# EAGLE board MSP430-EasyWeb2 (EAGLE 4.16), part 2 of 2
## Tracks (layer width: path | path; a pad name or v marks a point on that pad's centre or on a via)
317_+3.3V  (via drill 0.61)
  Top 1.016: v37.21,16.38 37.21,17.4 36.7,17.91 32.51,17.91 32,17.4 3.3.1
  Top 1.27: 34.8,8.64 36.58,8.64 36.83,8.89 VR2.2 | 34.8,8.64 R54.2 | C30.2 34.8,8.64
  Bottom 1.27: v37.21,16.38 37.21,13.84 36.07,12.7 36.07,9.65 36.83,8.89 VR2.2
+3.3V  (via drill 0.81)
  Top 0.254: IC2.9 35.29,52.61 35.79,52.11 35.79,51.11 | 35.79,50.11 IC2.14 32.04,50.11 C20.1 | 35.79,50.11 35.79,51.11 | 35.79,51.11 IC2.12 | IC2.16 35.04,49.11 35.79,49.11 | 35.79,49.11 35.79,50.11 | 35.66,46.11 IC2.22 34.37,46.11 32.04,46.11 32.04,46.57 | 35.66,46.11 37.04,44.61 37.04,42.22 | IC2.29 | 37.54,42.22 IC2.29 | 37.04,42.22 IC2.28 | 37.04,42.22 37.54,42.22 | 35.79,48.9 35.66,46.11 | 35.79,48.9 35.79,49.11 | 32.04,46.57 32.04,46.61 | 32.04,46.57 C19.1 | 43.54,56.36 41.54,56.36 41.04,56.86 IC2.90 41.04,59.36 40.79,59.61 38.79,59.61 38.54,59.36 IC2.95 | IC2.85 | 43.54,56.36 IC2.85 | 48.04,56.36 IC2.76 48.04,58.97 48.79,59.72 48.79,60.64 R4.2 | 48.04,56.36 43.54,56.36 | 45.54,42.1 45.54,41.11 45.8,40.61 C16.1 46.46,40.61 47.04,40.61 47.54,41.11 IC2.49 | 45.54,42.1 IC2.45 | 45.54,42.1 46.04,42.1 IC2.46 46.04,47.11 | IC2.49 | 48.04,53.61 48.04,56.36 | 48.04,53.61 IC2.69 56.62,53.61 C23.1 | 46.04,47.11 46.04,50.11 48.04,52.11 48.04,53.61 | C22.1 37.68,40.61 37.54,40.61 IC2.29 | 41.04,44.36 IC2.36 | 41.04,44.36 38.04,44.36 37.54,43.86 37.54,42.22 | C21.1 52.04,47.26 52.04,47.11 | 52.04,47.11 IC2.56 48.54,47.11 46.04,47.11 | 52.04,45.72 52.04,45.61 | 52.04,45.72 C18.1 | 52.04,47.11 52.04,45.72 | 41.04,44.36 41.04,45.11 43.04,47.11 46.04,47.11 | v36.2,48.89 35.79,48.9
  Top 0.61: R4.2 C17.1
  Top 1.016: v32.51,19.68 31.62,19.68 30.86,18.92 3.3.2 | EXT.8 46.99,77.47 45.72,76.2 40.64,76.2 40.01,76.83 LINK.A
  Top 1.27: LAN.A LINK.A
  Bottom 1.016: 30.99,19.68 30.99,48.89 | 30.99,19.68 25.65,19.68 22.1,16.13 22.1,15.24 19.56,12.7 18.41,12.7 13.97,8.25 POWER.A | 30.99,19.68 v32.51,19.68 | 30.99,48.89 29.34,48.89 24.77,53.47 24.77,61.72 16.89,69.6 16.89,73.91 15.88,74.93 LAN.A | 30.99,48.89 v36.2,48.89
  pour Top (isolate 0.762, hatched): 35.56,60.33 35.56,44.45 55.88,44.45 55.88,64.14 41.91,64.14 41.91,60.33
+3.6V  (via drill 0.61, 0.81)
  Top 0.254: IC1.64 | 91.54,57.24 91.57,57.28 91.4,57.11 IC1.64 | 93.16,59.51 93.22,59.57 C14.1 | R8.2 94.23,52.32 94.23,52.58 | IC1.1 89.04,59.42 89.18,59.56
  Top 0.406: 91.54,57.24 91.54,58.89 91.54,59.56 | 91.54,59.56 89.18,59.56 89.15,59.56 | 93.22,59.57 93.22,59.56 91.54,59.56
  Top 0.61: R13.2 74.93,34.92 | 74.93,34.92 R37.2 | 74.93,34.92 U3.8 | U3.3 87.5,37.46 91.57,33.4 R14.2 91.44,32.51 | v96.14,52.58 94.23,52.58 | 93.26,59.69 C14.1 | 95.72,59.69 C13.1
  Top 0.813: U1.16 16.51,27.3 17.14,26.67 17.14,25.4 | 17.14,25.4 C15.1 | v17.14,23.49 17.14,25.4
  Top 1.016: R33.2 111.12,40.85 111.12,39.5 110.36,38.73 109.09,38.73 108.59,38.23 108.59,33.53 | 108.59,33.53 91.57,33.53 91.61,32.6 R14.2 | 108.59,31.24 R30.2 | 64,32.72 v64.01,31.62 | 108.59,10.79 108.59,5.08 106.05,2.54 100.97,2.54 100.33,3.17 JTAG.4 | 108.59,12.06 108.59,10.79 | 108.59,10.79 R24.2 | 108.59,21.08 R27.2 | 108.46,12.06 108.59,12.06 | 108.59,12.06 108.59,21.08 | 108.59,21.08 108.59,31.24 | 108.59,31.24 108.59,33.53 | 22.61,18.92 3.6.2
  Top 1.27: 47.62,32.73 58.54,32.71 R12.2 64,32.72 74.54,32.71 R13.2 | 47.62,32.73 R11.2 | 22.61,18.92 21.59,19.94 21.59,23.49 | v20.95,23.49 21.59,23.49 | 21.59,23.49 24.89,23.49 25.53,24.13 25.53,25.15 27.05,26.67 45.97,26.67 47.62,28.32 47.62,32.73 | 108.46,12.06 81.92,12.06 79.38,14.61 65.41,14.61 64.56,13.75 R34.2 64.56,11.85 62.87,10.16 D8.K | 94.49,59.69 93.26,59.69 | v94.49,60.33 94.49,59.69 | 94.49,59.69 95.72,59.69
  Bottom 0.61: 97.03,60.33 97.03,53.47 v96.14,52.58 | 97.03,60.33 97.03,65.41 92.58,69.85 92.58,73.03 97.79,78.23 AEXT.1 | 97.03,60.33 v94.49,60.33
  Bottom 0.813: v17.14,23.49 v20.95,23.49
  Bottom 1.016: v64.01,31.62 64.01,17.65 60.96,14.61 D8.K | AEXT.1 97.79,80.01 96.52,81.28 44.45,81.28 | 44.45,81.28 EXT.9 | 13.34,76.83 STATUS.A | 13.34,76.83 13.34,80.64 13.97,81.28 44.45,81.28 | 13.34,76.83 13.34,70.48 20.95,62.86 20.95,48.51 17.14,44.7 v17.14,23.49
+5V
  Top 1.016: LCD1.2 29.21,72.39 30.86,74.04 30.86,74.68 R38.2
  Top 1.27: C28.2 17.01,6.23 VR3.1
  Bottom 1.016: LCD1.2 29.21,69.85 30.48,68.58 47.24,68.58 47.24,73.28 49.53,75.56 EXT.7
  Bottom 1.27: VR3.1 17.14,6.1 17.14,8.25 18.41,9.52 26.04,9.52 31.11,14.61 31.11,15.88 36.2,20.95 36.2,43.18 47.24,54.23 47.24,68.58
+12V  (via drill 0.81)
  Top 1.27: 22.35,8.68 C27.2 | 22.35,8.68 22.35,12.06 20.07,14.35 C11.+ | D3.C 36.7,21.59 39.24,19.05 41.91,19.05 | 41.91,19.05 D10.K | VR1.3 29.97,5.84 29.97,7.37 28.66,8.68 C12.1 | VR3.3 21.84,6.22 21.84,8.64 22.35,8.68 | v105.28,30.73 105.28,23.37 103.51,21.59 95.89,21.59 93.35,19.05 41.91,19.05
  Bottom 1.27: VR1.3 29.21,4.32 27.81,2.92 21.97,2.92 20.7,4.19 VR3.3 | 105.28,44.83 102.87,47.24 LR2.A 101.6,48.89 100.33,50.16 100.33,52.7 102.23,54.61 106.05,54.61 107.32,55.88 107.32,62.23 | 105.28,44.83 REL2.1 | REL1.1 111.12,62.61 111.12,62.23 107.32,62.23 | 107.32,62.23 107.32,62.86 106.68,63.5 104.78,63.5 102.87,65.41 LR1.A 101.6,67.94 100.97,68.58 100.97,72.39 105.41,76.83 107.32,76.83 D5.K | C11.+ 20.07,18.16 D3.C | 105.28,40.64 D6.K | v105.28,30.73 105.28,40.64 | 105.28,40.64 105.28,44.83
/IOR  (via drill 0.61)
  Top 0.254: IC1.34 82.04,46.61 81.29,45.86 74.29,45.86 72.54,44.11 71.54,44.11 64.04,36.61 59.54,36.61 59.04,36.11 v58.04,36.11 | v57.79,48.86 56.06,48.86 55.31,49.61 IC2.61
  Bottom 0.254: 58.04,48.61 v57.79,48.86
  Bottom 0.406: v58.04,36.11 58.04,48.61
/IOW  (via drill 0.61)
  Top 0.254: IC1.35 82.54,46.61 82.54,46.36 81.54,45.36 74.79,45.36 72.79,43.36 71.79,43.36 64.04,35.61 v60.67,35.61 | IC2.62 | v58.54,50.11 IC2.62
  Bottom 0.406: v60.67,35.61 59.04,37.24 59.04,49.61 v58.54,50.11
A0
  Top 0.254: IC1.28 | IC1.28 71.54,51.61 67.54,47.61 62.54,47.61 62.54,46.99 R40.1
A1
  Top 0.254: IC1.29 | IC1.29 72.04,51.11 65.54,44.61 65.28,44.61 | R41.1 62.54,44.62
  Top 0.61: 62.54,44.62 65.28,44.61
A2
  Top 0.254: IC1.30 | IC1.30 72.54,50.61 64.04,42.11 63.5,42.11
  Top 0.61: R42.1 62.61,41.91 62.61,42.11 63.5,42.11
A3
  Top 0.254: IC1.31 | IC1.31 73.04,50.11 62.54,39.61 62.54,39.41 R43.1
AI0  (via drill 0.61)
  Top 0.254: IC1.59 92.29,54.61 93.29,55.61 95.54,55.61 v95.79,55.86
  Bottom 0.254: v95.79,55.86 95.79,57.11 93.29,59.61 93.29,67.73 | 95.29,78.06 AEXT.2
  Bottom 0.406: 93.29,67.73 91.52,69.51 91.52,73.86
  Bottom 0.61: 91.52,73.86 95.29,77.63 95.29,78.06
AI1  (via drill 0.61)
  Top 0.254: IC1.60 92.04,55.11 93.17,56.24 94.17,56.24 v94.54,56.61
  Bottom 0.254: v94.54,56.61 94.54,57.36 92.69,59.21 92.69,67.08
  Bottom 0.406: 92.69,67.08 90.64,69.13 90.64,74.33 90.64,74.64
  Bottom 0.61: AEXT.3 92.71,76.71 90.64,74.64
AI2  (via drill 0.61)
  Top 0.254: IC1.61 83.04,55.61 80.42,58.23 80.42,58.73 79.08,60.07 78.23,60.07 78.14,60.12 v78.14,60.25
  Bottom 0.406: 84.09,69.87 77.55,69.87 75.54,67.86 75.54,61.87 77.17,60.25 v78.14,60.25
  Bottom 0.61: 84.09,69.87 90.17,75.95 AEXT.4
AI3
  Top 0.254: IC1.2 | IC1.2 88.54,70.21 87.63,71.12
  Top 0.66: 87.63,71.12 AEXT.5
AI4
  Top 0.254: IC1.3 | IC1.3 88.04,69.11 85.04,72.11 | 85.04,78.05 AEXT.6
  Top 0.66: 85.04,72.11 85.04,78.05
AI5
  Top 0.254: IC1.4 | IC1.4 87.54,68.11 82.54,73.11 | 82.54,78.09 AEXT.7
  Top 0.66: 82.54,73.11 82.54,78.09
AI6
  Top 0.254: IC1.5 | IC1.5 87.04,67.11 80.04,74.11 | 80.04,78.71 AEXT.8
  Top 0.66: 80.04,74.11 80.04,78.71
AI7
  Top 0.254: IC1.6 | IC1.6 86.54,66.11 77.54,75.11 | 77.54,78.03 AEXT.9
  Top 0.66: 77.54,75.11 77.54,78.03
B1
  Top 0.254: IC1.40 | IC1.40 85.04,43.86 84.29,43.11 79.54,43.11 78.54,42.11 71.54,42.11 64.04,34.61 51.54,34.61 50.54,35.61 40.54,35.61
  Top 0.406: 39.54,34.61 40.54,35.61
  Top 0.813: 39.54,31.86 39.54,34.61 | 40.37,31.03 40.64,31.03
  Top 1.016: R11.1 40.64,31.03 B1.P$2 | 40.37,31.03 39.54,31.86
B2  (via drill 0.61)
  Top 0.254: IC1.41 85.54,43.61 84.54,42.61 79.79,42.61 78.79,41.61 72.42,41.61 v65.3,34.49
  Top 1.016: R12.1 57.15,29.76 B2.P$2
  Bottom 0.61: v65.3,34.49 61.54,34.49 57.15,30.1 B2.P$2
B3  (via drill 0.61)
  Top 0.254: IC1.42 86.04,43.36 84.79,42.11 80.04,42.11 79.04,41.11 73.18,41.11 71.04,38.98
  Top 0.406: v71.04,34.54 71.04,38.98
  Top 1.016: B3.P$2 73.66,29.59 74.93,30.86 R13.1
  Bottom 0.762: B3.P$2 72.14,29.21 71.04,30.31 v71.04,34.54
B4  (via drill 0.61)
  Top 0.254: IC1.43 86.54,43.11 84.91,41.48 80.91,41.48 v80.54,41.11
  Top 1.016: R14.1 91.57,30.61 B4.P$2
  Bottom 0.762: B4.P$2 85.85,29.21 80.54,34.52 80.54,35.89
  Bottom 0.813: 80.54,35.89 v80.54,41.11
D0  (via drill 0.61)
  Top 0.254: IC1.44 | IC1.44 87.04,42.86 85.04,40.86 81.66,40.86 80.92,40.11 v73.54,40.11 | 62.54,49.61 62.54,49.57 R44.1
  Top 0.406: 62.54,49.61 v68.04,49.61
  Bottom 0.406: v73.54,40.11 72.54,41.11 72.54,43.23 68.04,47.73 v68.04,49.61
D1  (via drill 0.61)
  Top 0.254: IC1.45 | IC1.45 87.54,42.61 85.16,40.23 82.04,40.23 81.42,39.61 74.54,39.61 74.04,39.11 v72.54,39.11
  Top 0.406: v66.54,51.11 65.54,52.11
  Top 0.61: R45.1 62.54,52.11 65.54,52.11
  Bottom 0.406: v72.54,39.11 71.04,40.61 71.04,42.34 66.54,46.84 v66.54,51.11
D2  (via drill 0.61)
  Top 0.254: IC1.46 88.04,48.61 87.92,48.73 81.41,48.73 79.54,46.86 73.29,46.86 72.79,46.36 v72.29,46.36
  Top 0.406: 65.29,54.61 v68.29,51.61
  Top 0.61: R46.1 65.29,54.61
  Bottom 0.406: v72.29,46.36 69.8,48.85 69.8,50.1 v68.29,51.61
D3  (via drill 0.61)
  Top 0.254: IC1.47 88.54,48.86 88.05,49.35 81.28,49.35 79.54,47.61 74.54,47.61 74.29,47.86 v73.54,47.86
  Top 0.406: 62.71,57.02 62.62,57.11 | 65.79,57.02 v66.94,55.84
  Top 0.61: 62.62,57.11 R47.1 | 62.71,57.02 65.79,57.02
  Bottom 0.406: v66.94,55.84 66.94,55 71.5,50.42 71.5,49.9 v73.54,47.86
D4  (via drill 0.61)
  Top 0.254: IC1.48 89.04,49.11 88.18,49.98 81.16,49.98 79.79,48.61 v75.29,48.61 | 62.66,59.61 R48.1
  Top 0.406: v69.54,54.36 69.54,55.36 65.29,59.61
  Top 0.61: 62.66,59.61 65.29,59.61
  Bottom 0.406: v69.54,54.36 v75.29,48.61
D5  (via drill 0.61)
  Top 0.254: IC1.49 91.54,49.61 92.04,49.11 92.04,48.48 91.54,47.98 v91.04,47.98
  Top 0.406: 64.42,62.23 65.92,60.73 68.99,60.73 69.09,60.83 v69.04,60.86
  Top 0.61: R49.1 64.42,62.23
  Bottom 0.406: v91.04,47.98 89.92,46.86 89.92,43.56 89.41,43.05 87.5,43.05 86.49,44.07 86.49,44.96 83.31,48.13 81.79,48.13 81.79,48.11 v69.04,60.86
D6  (via drill 0.61)
  Top 0.254: IC1.50 92.04,50.11 92.79,49.36 92.79,47.7 92.08,46.99 v92.07,47 v92.06,47 | 62.74,64.61 R50.1
  Top 0.406: v67.04,61.86 64.29,64.61
  Top 0.61: 64.29,64.61 62.74,64.61
  Bottom 0.254: v67.04,61.86 67.04,60.36 80.66,46.74 82.8,46.74 84.71,44.83 84.71,43.56 86.61,41.66 89.92,41.66 92.06,43.8 v92.06,47
D7  (via drill 0.61)
  Top 0.254: IC1.51 92.29,50.61 93.54,49.36 93.54,46.68 92.84,45.97 v91.02,45.97 v91.02,45.98 | 62.54,67.11 62.54,67.27 R51.1
  Top 0.406: v68.04,62.86 63.79,67.11
  Top 0.61: 63.79,67.11 62.54,67.11
  Bottom 0.254: v68.04,62.86 68.04,60.36 81.04,47.36 81.79,47.37 83.06,47.37 85.47,44.96 85.47,43.69 86.87,42.29 89.66,42.29 90.93,43.56 90.93,45.98 v91.02,45.98
DALLAS  (via drill 0.61)
  Top 0.254: IC1.19 77.29,56.11 v76.79,56.61
  Top 0.813: R35.2 71.75,13.11 v72.82,13.11
  Bottom 0.254: v76.79,56.61 69.54,63.86 67.29,63.86 66.04,62.61 66.04,60.36 77.29,49.11 77.29,42.61 78.79,41.11 78.79,35.23
  Bottom 0.406: 75.57,32.01 78.79,35.23
  Bottom 0.61: v72.82,13.11 72.82,15.99 70.95,17.86 70.95,25.13 72.36,26.54 74.42,26.54 75.57,27.69 75.57,32.01
DI1  (via drill 0.61)
  Top 0.254: IC1.13 83.04,60.51 81.54,62.01 v81.54,63.5
  Top 1.27: v114.55,10.16 113.92,10.79 R24.1
  Bottom 0.254: 81.53,62.74 81.54,63.11 v81.54,63.5 | 102.16,29.73 102.16,38.78 102.79,39.42 102.79,43.11 97.54,48.36 96.06,48.36 84.73,59.69 83.95,59.69 81.53,62.1 81.53,62.74 | 81.53,62.74 81.53,62.86
  Bottom 0.406: 102.16,29.73 104.79,27.1 104.79,9.48 105.41,8.86 114.55,8.86
  Bottom 1.27: OK1.5 119.38,9.14 118.62,8.38 114.55,8.38 114.55,8.86 v114.55,10.16
DI2  (via drill 0.61)
  Top 0.254: IC1.14 82.54,60.26 80.54,62.26 80.54,64.67 80.52,64.64 v80.54,64.74
  Top 1.27: R27.1 113.67,21.08 v114.43,20.32
  Bottom 0.254: v80.54,64.74 82.07,64.74 82.55,64.26 82.55,62.1 84.33,60.33 85.09,60.33 96.31,49.11 97.91,49.11 103.53,43.49 103.53,39.02 103,38.48 103,30.1 112.78,20.32 113.54,20.32 113.7,20.32 113.8,20.32 114.43,20.33 v114.43,20.32
  Bottom 1.016: OK2.5 119.38,19.68 118.24,18.54 116.21,18.54 v114.43,20.32
DI3  (via drill 0.61)
  Top 0.254: IC1.15 82.04,59.96 79.79,62.21 79.79,64.23 79.04,64.97 v79.04,65.37
  Top 1.27: v114.43,30.48 113.67,31.24 R30.1
  Bottom 0.254: v79.04,65.37 v79.04,65.36 79.38,65.66 79.46,65.74 82.05,65.74 83.57,64.22 83.57,62.1 84.71,60.96 85.34,60.96 96.44,49.86 98.29,49.86 104.16,43.99 104.16,38.62 103.63,38.1 103.63,30.61 103.65,30.61 105.65,28.61 109.04,28.61 109.13,28.7 114.43,28.7
  Bottom 0.813: OK3.5 119.38,29.84 118.24,28.7 114.43,28.7 v114.43,30.48
DI4  (via drill 0.61)
  Top 0.254: IC1.16 81.54,59.61 79.12,61.98 79.12,62.54 78.66,63 v78.66,63.75 | 113.29,42.61 113.29,42.55
  Top 0.406: v101.79,42.61 113.29,42.61
  Top 1.27: OK4.5 119.38,41.27 118.11,42.55 113.29,42.55 113.28,41.53 R33.1
  Bottom 0.254: v101.79,42.61 101.8,42.61 96.93,47.48 96.06,47.48 84.49,59.05 83.57,59.05 78.87,63.75 78.67,63.75 v78.66,63.75
E
  Top 0.254: IC1.23 74.54,54.11 73.54,55.11 73.54,65.61 64.89,74.26 51.02,74.26 47.88,71.12 47.62,71.12
  Top 0.61: LCD1.6 47.62,71.12
ETH_RES
  Top 0.254: IC2.75 50.54,56.61 52.66,58.73 52.66,62.36 | 51.54,62.36 51.45,62.44 C17.2 | 54.04,62.36 53.98,62.42 R9.2
  Top 0.813: 51.54,62.36 52.66,62.36 54.04,62.36
FREQ  (via drill 0.61)
  Top 0.254: IC1.12 83.54,58.11 83.29,57.86 81.54,57.86 81.04,58.36 81.04,59.16 80.85,59.36 78.49,61.72 78.52,61.75 v78.15,61.75 v78.16,61.75
  Top 1.27: R36.2 74.3,12.28 FREQ.2
  Bottom 0.254: v78.16,61.75 78.83,61.75 82.92,57.66 84.01,57.66 94.81,46.86 94.87,46.74 94.87,43.94 91.31,40.39 88.9,40.39 88.01,39.5 88.01,39.37
  Bottom 0.406: 92.2,21.27 92.2,30.61 88.01,34.8 88.01,39.37
  Bottom 0.762: 76.01,5.08 92.2,21.27
  Bottom 1.016: FREQ.2 76.01,5.08
GND  (via drill 0.61, 0.64, 0.81)
  Top 0.254: IC2.89 | IC2.89 41.54,57.36 41.91,56.99 42.67,56.99 43.04,57.36 IC2.86 43.04,61.52 43.81,62.29 | IC2.89 41.54,59.61 41.54,59.86 41.16,60.24 38.67,60.24 38.04,59.61 IC2.96 38.04,57.37 38.29,57.11 38.79,57.11 39.04,57.36 IC2.94 | IC2.1 33.66,56.61 33.66,56.11 34.04,56.11 IC2.2 33.29,56.11 33.02,55.84 33.02,54.11 | 33.53,53.61 IC2.7 33.02,53.61 | 33.53,53.11 IC2.8 33.02,53.11 | IC2.10 32.79,52.11 33.02,52.11 33.02,53.11 | 33.28,45.11 IC2.24 | 33.28,45.11 33.28,44.61 IC2.25 35.54,44.61 36.04,44.11 36.04,42.22 | IC2.23 33.28,45.61 33.28,45.11 | C19.2 32.04,45.11 33.28,45.11 | IC2.27 | IC2.27 36.54,42.22 36.04,42.22 | 36.04,42.22 IC2.26 | IC2.41 | 43.54,40.7 C16.2 | 43.54,40.7 43.54,42.09 | 43.54,42.09 IC2.41 | IC2.41 43.54,43.11 43.54,42.09 | 43.54,42.09 44.04,42.09 | 44.04,42.09 IC2.42 | 44.04,42.09 44.54,42.09 | IC2.43 44.54,43.11 44.54,42.09 | IC2.44 45.04,42.09 44.54,42.09 | 50.04,44.61 IC2.51 48.42,44.61 48.04,44.23 48.04,43.94 | 50.04,44.61 50.04,45.11 | 50.04,45.11 IC2.52 | 50.04,45.11 50.04,45.61 | 50.04,45.61 IC2.53 | 50.04,45.61 50.04,46.11 | IC2.55 50.04,46.61 50.04,46.11 | 50.04,46.11 | 50.04,46.11 IC2.54 | IC2.57 50.04,47.61 50.04,48.11 | 50.04,48.11 IC2.58 | IC2.58 | 50.04,48.61 50.04,48.11 | 50.04,49.11 IC2.60 48.79,49.11 48.54,49.36 48.54,50.36 48.79,50.61 IC2.63 | 50.04,48.61 IC2.59 | 50.04,49.11 50.04,48.61 | 50.04,45.11 | 52.54,54.11 IC2.70 54.04,54.11 | 52.54,54.11 | C23.2 55.24,54.61 55.16,54.11 54.04,54.11 | 54.04,54.11 52.54,54.11 | C22.2 36.2,40.64 36.54,40.93 IC2.27 | 43.54,40.7 43.54,39.61 43.79,39.36 47.29,39.36 48.04,40.11 IC2.50 48.04,43.94 | 50.04,49.11 | 50.04,44.61 50.54,44.61 50.54,44.11 51.04,43.61 53.13,43.61 53.55,44.03 C18.2
  Top 0.254: 50.54,49.11 50.04,49.11 | 50.54,49.11 | IC1.62 | IC1.62 92.05,56.11 92.05,56.61 | IC1.63 | 92.05,56.61 IC1.63 | 46.35,62.48 R5.2 46.35,62.29 | 54.04,54.11 | v54.04,54.61 54.04,54.11 | 92.16,56.61 92.05,56.61 | 89.92,56.61 83.79,56.61 v83.57,56.64 | IC1.63 89.92,56.61 89.92,56.62 89.92,56.6 89.92,56.61 | 89.92,56.61 91.04,56.61 | IC2.21 33.27,46.61 33.15,46.74 33.15,47.11 | 33.15,47.11 IC2.20 | 33.15,47.61 33.15,47.11 | 33.15,47.61 IC2.19 | IC2.18 33.15,48.11 33.15,47.61 | 50.54,49.11 53.25,49.11 53.55,48.81 C21.2 | 98.17,37.21 95.89,37.21 v95.89,35.56 v100.84,35.56 | 33.02,54.11 IC2.6 | 33.02,53.61 33.02,54.11 | 33.02,53.11 33.02,53.61 | IC2.47 46.54,41.85 46.61,41.78 46.99,41.78 47.04,41.83 IC2.48 47.04,43.87 47.12,43.94 48.04,43.94
  Top 0.305: 82.55,38.73 82.55,38.74 82.55,38.48
  Top 0.406: 32.79,52.11 32.42,52.11 32,51.69 31.75,51.69 C20.2 | 92.16,56.61 92.79,57.24 92.79,57.61 C14.2 | 28.83,53.98 C2.2 | 32.26,48.11 33.15,48.11
  Top 0.61: 20.07,36.2 U1.8 | C9.2 25.18,36.74 | C13.2 95.57,58.27 93.41,58.27 C14.2 | 36.83,69.22 40.64,69.22 43.81,66.04 43.81,64.77 | 43.81,64.77 43.81,62.29 46.35,62.29 | U3.7 82.55,36.2 U3.2 | 85.73,38.73 U3.4 82.55,38.73 | 19.05,28.58 U1.15 | 15.88,34.92 U1.10 14.61,34.92 14.1,35.43 14.1,39.78 | 43.81,64.77 54.61,64.77 | 54.61,64.77 55.5,63.88 55.5,61.09 55.12,60.71 53.98,60.71 | 54.61,64.77 v54.61,66.42 | 20.19,18.29 C31.- | 82.55,34.92 U3.1 | 25.36,29.55 C10.2 | C18.2 C21.2
  Top 0.66: 25.18,36.74 26.42,37.97 27.69,37.97 28.57,37.08 28.57,31.92 28.03,31.37 27.18,31.37 25.36,29.55 | U1.8 C9.2
  Top 0.813: 19.05,25.4 19.05,28.58 19.05,35.05 20.07,36.2 | 88.14,38.73 89.66,37.21 93.47,37.21 | 93.47,37.21 98.17,37.21 99.19,38.23 99.19,43.56 98.07,44.68 98.07,52.45 98.04,52.48 98.04,54.23 C6.2 | 82.55,38.73 87.5,38.73 | 88.14,38.73 88.14,38.74 | R9.1 53.98,60.71 54.04,60.64 | C32.1 87.5,40.39 87.5,38.73 | 87.5,38.73 88.14,38.73 | 29.97,48.11 32.26,48.11 | 93.47,37.21 C33.1
  Top 1.016: v39.37,74.93 R39.1 37.72,74.89 37.72,72.64 36.83,71.75 LCD1.5 36.83,69.22 26.67,69.22 | C19.2 31.75,44.83 29.97,44.83 29.97,48.11 29.97,51.65 | OK1.4 R23.1 | OK2.4 R26.1 | OK3.4 R29.1 | OK4.4 R32.1 | PWR.-- 9.4,7.75 | EXT.10 41.91,80.01 43.18,81.28 66.04,81.28 67.31,80.01 AEXT.13 | 98.08,57.95 C13.2 | 98.08,57.95 98.43,58.29 v98.43,59.05 98.43,60.96 96.52,62.86 C5.1 C4.2 | 98.07,52.45 98.08,57.95 | 26.67,69.22 26.67,67.94 22.86,64.14 C3.2 | 26.67,69.22 LCD1.1 | 54.04,60.64 v54.04,59.61 | C3.2 | C3.2 22.86,53.21 22.86,51.65 | 22.86,51.65 v22.86,49.91 19.05,46.1 17.14,46.1 14.1,42.93 14.1,39.78 RS232.5 11.79,39.78 11.18,40.39 7.24,40.39 6.22,39.37 PWR.- | 22.86,51.65 28.83,51.65 | 28.83,51.65 29.97,51.65 | 28.83,51.65 28.83,53.98 | R10.1 7.49,8 | 29.97,51.65 C20.2 | 19.05,18.29 20.19,18.29 | v56.39,45.09 C18.2
  Top 1.27: 24.13,2.67 R52.1 | 16.51,10.41 C28.1 17.11,10.41 16.51,10.41 | 16.51,10.41 18.8,10.41 | 18.8,10.41 C27.1 | 16.51,10.41 C11.- 19.05,18.29 19.05,25.4 C15.2 | T1.1 R17.1 | T2.1 R20.1 | 18.8,10.41 18.8,7.62 VR3.2 | 14.99,9.52 15.88,10.41 16.51,10.41 | 64.14,2.67 DALLAS.1 | 64.14,2.67 71.76,2.67 | D9.A 78.11,5.21 75.57,2.67 71.76,2.67 | 71.76,2.67 FREQ.1 | R36.1 76.84,12.7 78.11,11.43 D9.A | D9.A 92.71,10.16 | 92.71,10.16 v106.17,10.16 | 82.55,38.48 82.55,38.73 82.55,36.2 82.55,34.92 82.55,24.13 | 34.8,2.67 32.26,2.67 R55.1 31.2,8.68 29.84,10.03 29.84,10.38 | 34.8,2.67 35.56,1.9 63.37,1.9 64.14,2.67 | 34.8,2.67 C30.1 | 82.55,24.13 81.41,24.13 78.49,21.21 73.66,21.21 | 82.55,24.13 B4.P$1 | B3.P$1 73.66,21.21 | B1.P$1 43.56,21.21 57.15,21.21 | 73.66,21.21 57.15,21.21 | 57.15,21.21 B2.P$1 | 92.71,10.16 JTAG.9 | 29.84,12.87 C26.2 | 29.84,12.87 C29.1 | 29.84,10.38 C12.2 | 29.84,10.38 29.84,12.87
  Top 1.676: 14.73,8 14.99,8
  Top 1.778: 32.26,2.67 24.13,2.67 17.4,2.67 14.99,5.08 14.99,8 14.99,9.52
  Top 2.184: PWR.-- 14.73,8
  Top 2.54: PWR.- 6.22,9.27 7.49,8 PWR.--
  Bottom 0.406: v54.04,59.61 v54.04,54.61
  Bottom 1.016: v39.37,74.93 39.37,75.56 EXT.10 | v98.43,59.05 105.41,59.05 | v56.39,45.09 56.39,37.85 54.23,35.69 54.23,27.05 B2.P$1
  Bottom 1.27: T2.1 105.41,59.05 T1.1 | OK4.4 124.46,40.64 126.37,38.73 126.37,30.48 | 126.37,30.48 OK3.4 | 126.37,20.32 126.37,30.48 | 126.37,20.32 OK2.4 121.92,19.05 119.76,16.89 115.57,16.89 113.79,18.67 108.59,18.67 107.32,17.4 107.32,11.3 v106.17,10.16 | 126.37,20.32 126.37,12.7 123.83,10.16 OK1.4 | FREQ.1 71.76,7.62 74.3,10.16 74.3,18.16 73.66,18.8 B3.P$1
  pour Bottom (isolate 0.61, rank 2, hatched): -0.63,-1.27 108.59,-1.27 108.59,40.64 103.51,40.64 103.51,82.55 -0.63,82.55
  pour Top (isolate 0.61, rank 2, hatched): -1.27,-1.27 107.7,-1.27 107.7,41.91 103.51,41.91 103.51,82.55 -1.27,82.55
GNDA
  Top 1.27: C25.1 7.26,72.39 6.86,72.39 RJ45.G1 RJ45.G2 4.95,51.44 C24.1
LANLED  (via drill 0.61)
  Top 0.254: IC2.100 36.04,59.11 35.67,59.48
  Top 0.305: 33.81,59.48 35.67,59.48
  Top 0.406: 33.81,59.48 32.18,61.11 30.68,61.11 v29.54,62.25
  Top 0.61: v24.89,68.2 24.89,72.26 25.65,73.03 27.56,73.03 28.14,73.62 R6.1
  Bottom 0.406: v29.54,62.25 29.59,62.23 29.59,63.25 29.57,63.52 29.08,64.01 v24.89,68.2
LCD_D4
  Top 0.254: IC1.24 74.04,53.61 72.79,54.86 72.79,65.36 64.57,73.58 64.44,73.66 54.61,73.66 54.47,73.58 | 52,71.11 52.01,71.12 LCD2.1
  Top 0.406: 52.01,71.12 54.47,73.58
LCD_D5
  Top 0.254: IC1.25 | IC1.25 73.54,53.11 72.04,54.61 72.04,65.11 63.99,73.16 63.99,73.15 56.52,73.15 56.42,73.03 | 54.5,71.11 LCD2.2
  Top 0.406: 54.5,71.11 56.42,73.03
LCD_D6
  Top 0.254: IC1.26 73.04,52.61 71.29,54.36 71.29,64.86 63.67,72.48 63.67,72.52 58.55,72.52 58.34,72.31
  Top 0.66: 58.34,72.31 LCD2.3
LCD_D7
  Top 0.254: IC1.27 72.54,52.11 70.54,54.11 70.54,64.61 64.04,71.11 62.24,71.11
  Top 0.61: 62.24,71.11 LCD2.4
LINKLED  (via drill 0.61)
  Top 0.254: IC2.99 36.54,59.48 36.54,59.61 36.04,60.11
  Top 0.305: v31.28,62.25 31.24,62.23 32.51,62.23 34.63,60.11 36.04,60.11
  Top 0.406: v31.37,79.63 R7.1
  Bottom 0.406: v31.28,62.25 31.28,63.66 25.01,69.92 25.01,72.25 27.69,74.93 29.21,74.93 31.37,77.09 v31.37,79.63
N$1
  Top 1.016: R10.2 11.21,2.32 POWER.K
N$2
  Top 0.66: R7.2 23.11,79.63 LINK.K
N$3
  Top 1.016: R6.2 15.11,74.93 14.1,75.95 14.1,78.11 15.37,79.38 LAN.K
N$4
  Top 2.54: D3.A 15.88,19.05 13.97,17.14 13.97,13.97 PWR.+
N$5
  Top 0.61: U1.1 23.49,27.3 23.71,27.09 C7.2
N$6
  Top 0.66: U1.4 25.4,31.12 26.54,32.26 26.54,32.8 C8.2
N$7
  Top 0.762: 26.8,59.05 TR.2
  Top 0.813: C2.1 26.16,54.9 26.16,58.42 26.8,59.05
N$8
  Top 0.762: TR.7 26.67,65.41 24.51,63.25 24.51,53.93
  Top 0.813: C3.1 24.51,53.93
N$9
  Top 0.254: IC2.97 37.54,60.11 39.15,61.72
  Top 0.406: 39.16,61.73 39.15,61.72 Q1.2
N$10
  Top 0.254: IC2.77 47.54,62.36 47.79,62.61 48.54,62.61 48.79,62.36 48.88,62.44 R4.1
N$11  (via drill 0.61)
  Top 0.254: IC2.93 39.54,56.86 v38.79,56.11
  Top 0.61: R5.1 45.72,60.11 v44.8,60.11
  Bottom 0.406: v38.79,56.11 39.79,56.11 43.79,60.11 v44.8,60.11
N$12
  Top 0.254: IC2.98 37.04,60.75
  Top 0.406: 37.04,60.75 36.19,61.59 36.06,61.72 Q1.1
N$13
  Top 1.27: C29.2 32.26,15.37 32.89,16 D10.A
  Bottom 1.27: D10.A 34.29,7.49 35.43,6.35 VR2.3
N$14
  Top 0.66: C9.1 26.54,35.85 26.54,35.05 26.16,34.67 24.42,34.67 23.41,33.66 U1.6
N$15
  Top 0.61: U1.13 14.61,31.12 13.72,32 13.72,32.64 RS232.3
N$16
  Top 0.66: U1.2 23.88,28.58 24.6,27.85 C10.1
N$17  (via drill 0.61)
  Top 1.016: R15.1 104.99,77.89 104.14,78.74 D5.A 100.84,77.98 100.84,68.33 v99.7,67.18
  Top 1.27: R15.1 109.22,74.93 109.22,74.55 REL1.2
  Bottom 1.016: T1.3 100.33,66.55 v99.7,67.18
N$18
  Top 1.27: 103.51,65.66 R16.2 | 103.51,65.66 R17.2 | 103.51,65.66 103.51,62.61 102.87,61.98 T1.2
N$19
  Top 0.61: STATUS.K 11.43,79.38 13.34,81.28 31.5,81.28 33.15,79.63 R21.2
N$20
  Top 1.016: R22.1 131.06,2.54 132.33,3.81 134.58,3.81 DIN1.1
N$21
  Top 0.66: C7.1 20.95,25.4 20.32,26.03 20.32,29.21 20.95,29.84 U1.3
N$22
  Top 1.27: R15.2 102.87,74.51 LR1.K
N$23
  Top 0.66: C8.1 24.42,32.38 U1.5
N$24
  Top 1.016: DIN1.2 132.04,8.85 130.05,6.86 128.65,6.86 | D1.A 128.7,6.86 128.65,6.86 | OK1.2 119.38,5.08 121.16,6.86 128.65,6.86
N$25
  Top 3.048: OUT1.3 125.05,72.94 REL1.O
  Bottom 3.048: REL1.O 125.05,72.94 OUT1.3
N$26
  Top 0.762: TR.10 19.68,65.41 20.32,66.04 | C25.2 15.24,70.87 17.78,68.33 19.3,68.33 20.31,67.31 20.32,66.55
  Top 0.813: 20.32,66.55 20.32,66.04
  Top 1.016: C25.2
N$27
  Top 3.048: OUT1.2 122.81,67.94 122.17,68.58 REL1.P
  Bottom 3.048: REL1.P 122.17,68.58 122.81,67.94 OUT1.2
N$28
  Top 0.61: RS232.2 13.77,29.84 U1.14
N$29
  Top 3.048: OUT1.1 123.78,62.94 REL1.S
  Bottom 3.048: REL1.S 123.78,62.94 OUT1.1
N$30
  Top 0.762: C24.2 18.41,51.44 20.31,53.33 20.31,58.42 19.68,59.05 TR.15
N$31
  Top 0.61: T2.3 99.19,56.01 99.19,45.59 100.33,44.45 | 103.51,44.45 R18.1 100.33,44.45 | D6.A 100.33,41.27 100.33,44.45
  Top 1.27: REL2.2 109.6,56.77 107.32,59.05 100.97,59.05 100.33,58.42 T2.3
N$32
  Top 0.61: LR2.K 104.14,51.44 104.78,50.8 104.78,44.45 R18.2
N$33
  Top 1.27: 103.51,53.72 R20.2 | R19.2 101.6,53.72 103.51,53.72 | 103.51,53.72 103.51,56.64 102.87,57.28 T2.2
N$34
  Top 1.016: DI1.K 110.49,4.45 112.4,2.54 OK1.1
N$35
  Top 3.048: OUT2.3 123.78,56.44 REL2.O
  Bottom 3.048: REL2.O 123.78,56.44 OUT2.3
N$36
  Top 3.048: OUT2.2 122.56,51.44 121.92,50.8 REL2.P
  Bottom 3.048: REL2.P 121.92,50.8 122.56,51.44 OUT2.2
N$37
  Top 3.048: OUT2.1 125.05,46.44 REL2.S
  Bottom 3.048: REL2.S 125.05,46.44 OUT2.1
N$38  (via drill 0.61)
  Top 1.016: 125.1,4.9 D1.C 125.35,4.83
  Top 1.27: R22.2 125.1,3.56 125.1,4.9 | v123.7,5.08 D1.C
  Bottom 1.27: DI1.A 114.3,5.08 v123.7,5.08
N$39
  Top 1.016: OK1.6 116.84,9.52 118.11,8.25 127,8.25 127.89,9.14 127.89,10.16 R23.2
N$40
  Top 1.27: R34.1 R35.1 69.64,10.16 D9.K D8.A 66.68,8.25 DALLAS.2
N$41  (via drill 0.61)
  Top 0.254: v86.36,52.58 86.87,53.09 88.27,53.09 89.41,51.94 89.92,51.94 90.25,51.61 IC1.53
  Top 0.406: C32.2 89.24,43.6 Q3.2
  Bottom 0.254: v86.36,52.58 86.36,46.48 Q3.2
N$42
  Top 1.016: R25.1 130.81,12.7 132.08,13.97 134.58,13.97 DIN2.1
N$43
  Top 1.016: DIN2.2 132.04,19.01 130.05,17.02 128.7,17.02 | 128.7,17.02 D2.A | OK2.2 119.38,14.61 121.79,17.02 128.7,17.02
N$44
  Top 1.016: DI2.K 110.49,14.61 112.4,12.7 OK2.1
N$45  (via drill 0.61)
  Top 1.27: 125.1,15.24 D2.C | R25.2 125.1,13.75 125.1,15.24 | v123.83,15.24 125.1,15.24
  Bottom 1.27: v123.83,15.24 114.3,15.24 DI2.A
N$46
  Top 1.016: R26.2 127.85,19.27 127,18.41 117.48,18.41 116.84,19.05 OK2.6
N$47
  Top 1.27: VR1.1 26.04,5.08 25.18,5.93 R52.2 R53.1
N$48
  Top 1.016: R28.1 131.44,22.86 132.72,24.13 134.58,24.13 DIN3.1
N$49
  Top 1.016: DIN3.2 132.04,29.17 130.05,27.18 128.7,27.18 | 128.7,27.18 D4.A | OK3.2 119.38,24.64 121.92,27.18 128.7,27.18
N$50
  Top 1.016: DI3.K 110.49,24.77 112.4,22.86 OK3.1
N$51  (via drill 0.61)
  Top 1.27: 125.1,25.4 D4.C | R28.2 125.1,23.91 125.1,25.4 | v123.83,25.4 125.1,25.4
  Bottom 1.27: v123.83,25.4 114.3,25.4 DI3.A
N$52
  Top 1.016: OK3.6 116.84,29.84 118.11,28.58 127,28.58 127.85,29.42 R29.2
N$53  (via drill 0.61)
  Top 1.016: R38.1 v34.29,74.93 R39.2
  Bottom 1.016: LCD1.3 31.75,71.75 34.29,74.3 v34.29,74.93
N$54
  Top 1.016: R31.1 130.81,33.02 132.08,34.29 134.58,34.29 DIN4.1
N$55
  Top 1.016: DIN4.2 131.41,39.33 129.41,37.34 128.7,37.34 | 128.7,37.34 D7.A | OK4.2 119.38,34.29 122.43,37.34 128.7,37.34
N$56
  Top 1.016: DI4.K 110.49,34.92 112.4,33.02 OK4.1
N$57  (via drill 0.61)
  Top 1.27: 125.1,35.56 D7.C | R31.2 125.1,34.08 125.1,35.56 | v123.83,35.56 125.1,35.56
  Bottom 1.27: v123.83,35.56 114.3,35.56 DI4.A
N$58
  Top 1.016: R32.2 127.85,39.59 127,38.73 117.48,38.73 116.84,39.37 OK4.6
N$60
  Top 0.406: R54.1 34.8,10.29
  Top 1.27: VR2.1 35.56,11.43 34.8,10.67 R54.1 R55.2
N$61  (via drill 0.61)
  Top 0.254: IC1.52 89.35,51.11 88.34,52.12 v87.76,52.12
  Top 0.406: C33.2 Q3.1
  Bottom 0.254: Q3.1 93.47,46.99 88.34,52.12 v87.76,52.12
N$62  (via drill 0.61)
  Top 0.254: IC1.38 84.04,45.05 v83.57,44.58
  Top 0.813: R56.1 95.04,28.49 93.22,26.67 88.52,26.67 85.98,29.21 v85.98,33.15
  Bottom 0.813: v85.98,33.15 83.57,35.56 v83.57,44.58
N$63
  Top 0.254: 100.97,27.18 BUZZER.+
  Top 0.813: R56.2 99.06,31.12 100.97,29.21 100.97,27.18
P2_0
  Top 0.254: IC1.20 76.29,55.61 75.79,56.11 75.79,67
  Top 0.406: EXT.1 64.77,78.02 75.79,67
P2_1  (via drill 0.61)
  Top 0.254: IC1.21 75.54,55.11 75.04,55.61 75.04,66.11 65.79,75.36 v47.03,75.36
  Top 0.61: R21.1 v36.7,79.63
  Bottom 0.61: v47.03,75.36 42.29,75.36 40.54,73.61 38.53,73.61 36.7,75.44 v36.7,79.63
P4_3  (via drill 0.61)
  Top 0.254: 100.69,16.11 BUZZER.- | IC1.39 84.54,44.11 84.04,43.61 78.54,43.61 v78.29,43.36
  Top 0.813: v83.56,16.09 83.54,16.11 100.69,16.11
  Bottom 0.254: 79.54,32.82 79.54,41.36 78.29,42.61 v78.29,43.36
  Bottom 0.406: 79.54,32.82 81.1,31.21 81.1,18.55 v83.56,16.09
RD+
  Top 0.61: RJ45.3 16.76,62.86
  Top 0.762: 16.76,62.86 17.27,62.36 17.27,60.83 17.78,60.33 TR.14
RD-
  Top 0.762: TR.16 17.27,57.78 16,59.05 RJ45.6
REL1  (via drill 0.61)
  Top 0.254: IC1.17 78.54,57.11 77.09,58.56 77.09,65.66 v78.79,67.36
  Top 0.406: R16.1 100.23,63.92 96.53,67.62 v89.54,67.61
  Bottom 0.406: v78.79,67.36 79.04,67.61 v89.54,67.61
REL2  (via drill 0.61)
  Top 0.254: IC1.18 78.29,56.61 76.45,58.45 76.45,67.02 v77.43,68
  Top 0.813: R19.1 101.39,55.25 v100.35,55.25
  Bottom 0.254: v100.35,55.25 100.43,55.25 96.81,51.5 95.69,51.5 92.09,55.1 92.09,66.55 90.03,68.61
  Bottom 0.406: v77.43,68 78.04,68.61 90.03,68.61
RS  (via drill 0.61)
  Top 0.254: IC1.22 75.04,54.61 74.29,55.36 74.29,65.86 65.34,74.81 49.24,74.81 47.07,72.64 43.94,72.64 v43.87,72.61
  Bottom 0.61: LCD1.4 34.29,71.63 35.27,72.61 v43.87,72.61
RST  (via drill 0.61)
  Top 0.254: R8.1 94.04,54.24 93.68,54.24 93.81,54.11 IC1.58 90.04,54.11 89.15,54.99 82.91,54.99 79.35,58.55 78.87,58.55 v78.79,58.62
  Top 0.813: 94.04,54.24 94.05,54.23 C6.1
  Bottom 0.254: 65.04,60.36 76.79,48.61 76.79,42.11 78.04,40.86 78.04,37.13
  Bottom 0.406: 65.04,60.36 65.04,64.61 | v78.79,58.62 76.27,58.62 71.01,63.75 70.99,63.75 70.15,64.61 65.04,64.61 | 65.04,64.61 65.04,73.39 | 78.04,37.13 78.04,36.51 77.47,35.94 69.98,35.94
  Bottom 0.61: 65.04,73.39 62.23,76.2 EXT.2
  Bottom 0.66: JTAG.11 90.17,8.36 89.17,9.36 84.79,9.36 78.29,2.86 70.29,2.86 69.29,3.86 69.29,5.97 67.31,7.96 66.68,8.64 66.68,32.64 69.98,35.94
RX0  (via drill 0.61)
  Top 0.254: 29.97,37.46 23.75,43.69 19.3,43.69 17.4,41.78 17.4,38.35 18.16,37.59 18.16,33.02 17.53,32.38 U1.12 | 63.9,37.46 66.79,40.36 v66.79,41.36 67.79,41.36 71.29,44.86 72.29,44.86 73.79,46.36 81.04,46.36 81.54,46.86 | 81.54,46.86 IC1.33 | 81.54,46.86
  Top 0.406: 29.97,37.46 63.9,37.46
  Bottom 0.406: v66.79,41.36 66.79,43.87 64.16,46.49 64.16,72.49
  Bottom 0.61: EXT.3 59.69,76.96 64.16,72.49
RXD+  (via drill 0.61)
  Top 0.254: 40.54,55.34 IC2.91
  Top 0.305: 40.54,55.34 39.54,54.34 37.81,54.34 34.79,57.36 v32.91,57.36
  Top 0.61: v32,59.82 30.48,59.82 R1.1 30.06,60.33
  Top 0.762: TR.3 30.06,60.33
  Bottom 0.406: v32.91,57.36 32.91,58.91 v32,59.82
RXD-
  Top 0.254: IC2.92 40.04,55.84 39.17,54.97
  Top 0.305: R1.2 30.44,58.2 30.6,58.36 34.66,58.36 38.06,54.97 39.17,54.97
  Top 0.762: TR.1 30.06,57.78
  Top 0.813: 30.06,57.78 R1.2
SA0  (via drill 0.61)
  Top 0.254: 60.26,47.61 R40.2 | IC2.37 41.54,41.86 41.04,41.36 40.04,41.36 v39.79,41.11
  Top 0.406: v55.54,47.61 60.26,47.61
  Bottom 0.406: v39.79,41.11 39.79,40.74 40.79,39.74 40.79,39.11 41.54,38.36 50.18,38.36 52.91,41.09 52.91,44.98 v55.54,47.61
SA1  (via drill 0.61)
  Top 0.254: IC2.38 42.04,41.61 39.79,39.36 v39.79,39.11 | 60.73,44.11 R41.2
  Top 0.406: v54.79,42.61 58.54,42.61 60.04,44.11 60.73,44.11
  Bottom 0.406: v39.79,39.11 39.75,38.86 41.5,37.11 51.21,37.11 54.79,40.69 v54.79,42.61
SA2  (via drill 0.61)
  Top 0.254: IC2.39 42.54,41.11 41.79,40.36 v41.79,39.61 | 60.73,42.06 R42.2
  Top 0.406: 60.73,42.06 60.73,41.48 v51.04,41.48
  Bottom 0.406: v41.79,39.61 49.17,39.61 v51.04,41.48
SA3
  Top 0.254: IC2.40 43.04,40.86 42.79,40.61 42.79,39.36 43.41,38.74 60.23,38.74 60.88,39.26 R43.2
SCL  (via drill 0.61)
  Top 0.254: U3.6 79.63,37.46 | IC1.37 | IC1.37 83.54,45.86 82.04,44.36 77.04,44.36 v75.79,43.11
  Top 0.61: U3.6 77.04,37.46 v77.04,37.36
  Bottom 0.406: v75.79,43.11 75.79,41.86 77.04,40.61 v77.04,37.36 75.84,37.36 75.44,36.96 62.65,36.96 60.17,39.44 60.17,56.95 49.15,67.97 49.15,73.03 52.07,75.95
  Bottom 0.61: 52.07,75.95 EXT.6
SD0
  Top 0.254: R44.2 60.96,49.53 61.04,49.61 59.04,51.61 IC2.65
SD1
  Top 0.254: R45.2 60.84,52.11 IC2.66 | IC2.66
SD2
  Top 0.254: IC2.67 59.04,52.61 61.04,54.61 R46.2
SD3
  Top 0.254: IC2.68 58.04,53.11 59.17,54.24 59.17,56.25 | 60.84,57.11 R47.2
  Top 0.66: 59.17,56.25 60.04,57.11 60.84,57.11
SD4
  Top 0.254: IC2.71 52.54,54.61 54.04,56.11 55.29,56.11 58.79,59.61 | 61.04,59.61 60.96,59.61 R48.2
  Top 0.61: 58.79,59.61 60.96,59.61
SD5
  Top 0.254: IC2.72 | IC2.72 52.04,55.11 53.79,56.86 54.79,56.86 60.04,62.11 | 61.04,62.11 61,62.11 R49.2
  Top 0.66: 60.04,62.11 61,62.11
SD6
  Top 0.254: IC2.73 51.54,55.61 53.54,57.61 54.54,57.61 58.54,61.61 58.54,63.61 | 60.72,64.61 R50.2
  Top 0.66: 58.54,63.61 59.54,64.61 60.72,64.61
SD7
  Top 0.254: IC2.74 | IC2.74 51.04,56.11 53.29,58.36 54.29,58.36 57.54,61.61 57.54,66.61 | 60.58,67.61 R51.2
  Top 0.66: 57.54,66.61 58.54,67.61 60.58,67.61
SDA  (via drill 0.61)
  Top 0.254: IC1.36 83.04,46.11 81.79,44.86 75.79,44.86 v74.04,43.11 | 74.93,37.08 R37.1
  Top 0.61: 74.93,37.08 75.04,37.08 v75.04,38.61 76.31,38.61 76.44,38.73 U3.5
  Bottom 0.406: v75.04,38.61 75.04,40.86 74.04,41.86 v74.04,43.11 | v75.04,38.61 v75.05,38.61 | 54.61,76.83 50.29,72.52 50.29,68.45 60.91,57.83 60.91,40.2 63.14,37.97 73.53,37.97 74.17,38.61 v75.04,38.61
  Bottom 0.61: 54.61,76.83 EXT.5
TCK  (via drill 0.61)
  Top 0.254: IC1.57 | IC1.57 92.29,53.61 92.79,53.11 92.79,51.61 95.8,48.6 95.8,45.98 v95.81,45.86
  Bottom 0.254: v95.81,45.86 95.83,45.88 95.89,45.83 95.76,45.7 95.76,43.81 91.69,39.75 89.72,39.75 89.12,39.15 89.03,38.99 89.04,39.1 89.04,39.07
  Bottom 0.406: 89.04,39.07 89.04,35.3 95.25,29.09 95.25,28.96
  Bottom 0.61: JTAG.7 95.25,28.96
TD+
  Top 0.762: TR.9 13.97,66.67 RJ45.1
TD-
  Top 0.762: RJ45.2 TR.11
TDI  (via drill 0.61)
  Top 0.254: v91.67,38.55 91.67,43.84 90.04,45.47 90.04,45.59 90.04,45.64 90.04,49.61 88.55,51.1 85.8,51.1 85.34,51.56 85.34,53.34 85.73,53.72 88.52,53.72 89.63,52.61 IC1.55
  Bottom 0.406: v91.67,38.55 91.67,35.66 98.04,29.29 98.04,10.54 98.01,10.51
  Bottom 0.66: 98.01,10.51 100.33,8.18 JTAG.3
TDO/TDI  (via drill 0.61)
  Top 0.254: IC1.54 92.04,52.11 92.29,51.86 92.29,51.36 94.29,49.36 94.29,45.46 94.3,45.47 94.3,45.4 96.9,42.8 97.79,42.8 v97.86,42.85
  Bottom 0.254: 97.92,42.8 v97.86,42.85
  Bottom 0.406: 97.92,42.8 95.89,42.8 93.35,40.26 93.35,35.34 99.04,29.65 99.04,11.35
  Bottom 0.66: 99.04,11.35 102.87,7.52 JTAG.1
TMS  (via drill 0.61)
  Top 0.254: v90.29,38.57 90.29,38.85 90.81,39.37 90.81,43.94 90.55,44.2 89.54,45.16 89.54,49.36 88.34,50.56 85.33,50.56 84.71,51.18 84.71,53.85 85.22,54.36 88.77,54.36 90.02,53.11 IC1.56
  Bottom 0.406: v90.29,38.57 90.29,35.55 97.03,28.81 97.03,9.02
  Bottom 0.66: 97.03,9.02 97.79,8.25 JTAG.5
TX0  (via drill 0.61)
  Top 0.254: U1.11 17.27,33.66 17.53,33.91 17.53,37.08 16.64,37.97 16.64,42.16 18.92,44.45 24.26,44.45 30.61,38.1 63.51,38.1 65.31,39.88 65.31,39.98 65.31,40.11 v65.29,40.36 65.29,41.36 73.54,49.61 IC1.32
  Bottom 0.406: v65.29,40.36 63.29,42.36 63.29,71.58
  Bottom 0.61: EXT.4 57.15,77.72 63.29,71.58
TXD2+
  Top 0.762: TR.8 30.48,66.67
  Top 1.016: C1.1 30.48,66.67 31.11,67.31 R3.2
TXD2-
  Top 0.762: C1.2 30.06,64.14 TR.6
  Top 1.016: R2.2 33.15,64.77 32.93,64.55 C1.2
TXD+
  Top 0.254: IC2.87 42.54,64.88
  Top 0.813: R3.1 40.11,67.31 42.54,64.88
TXD-
  Top 0.254: IC2.88 42.04,63.11 41.04,64.11
  Top 0.813: R2.1 40.13,65.02 41.04,64.11
VCCOUT
  Top 1.016: C26.1 28.32,14.86 3.6.1
  Top 1.27: VR1.2 26.54,6.98 25.91,7.62 25.91,10.41 | 25.91,10.41 25.91,11.81 26.5,12.41 26.5,14.44 C31.+ 26.92,14.61 29.43,14.61 C26.1 | R53.2 24.77,10.41 25.91,10.41
VE+  (via drill 0.61)
  Top 0.254: IC1.10 84.54,60.51 83.54,61.51 83.54,65.61 v76.64,72.52
  Bottom 0.61: v76.64,72.52 74.93,74.22 AEXT.10
VR+
  Top 0.254: IC1.7 | IC1.7 86.04,65.11 77.01,74.14
  Top 0.61: 77.01,74.14 75.08,74.14 72.39,76.83 AEXT.11
VR-
  Top 0.254: IC1.11 84.04,60.26 83.04,61.26 83.04,64.61 71.2,76.45
  Top 0.66: 71.2,76.45 69.85,77.8 AEXT.12
XIN  (via drill 0.61)
  Top 0.254: IC1.8 | IC1.8 85.54,60.98 85.09,61.46 v85.09,61.99
  Top 0.406: Q2.2 90.3,62.86 C5.2
  Bottom 0.254: v85.09,61.99 85.06,61.97 88.14,61.97 Q2.2
XOUT  (via drill 0.61)
  Top 0.254: 93.54,65.18 C4.1 | IC1.9 | IC1.9 85.04,60.76 84.17,61.63 84.17,62.82 Q2.1
  Top 0.406: 93.54,65.18 93.47,65.15 92.08,65.15 v90.58,66.64
  Bottom 0.254: 99.29,43.74 99.29,43.84 99.19,43.94 96.3,46.86 95.68,46.86 84.25,58.29 83.19,58.29 78.74,62.74 78.65,62.74 78.53,62.75 77.91,62.75 77.34,63.31 77.34,65.28 78.43,66.38 78.54,66.36 79.7,66.36 79.98,66.64 84.84,66.64 | 84.84,66.64 v90.58,66.64 | 84.84,66.64 Q2.1
  Bottom 0.406: 99.29,43.74 99.31,43.72 99.31,31.37 99.42,31.23 103.54,27.11 103.54,9.11 105.29,7.36 105.29,3.61 104.54,2.86 99.38,2.86 JTAG.6

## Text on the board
Top: TOP
Bottom: BOTTOM | HTTP://WWW.OLIMEX.COM/DEV
tPlace: GND | 3.6 | 3.3 | 5V | SCL | SDA | TX0 | RX0 | RST | P20 | GND | VR- | VR+ | VE+ | AI7 | AI6 | AI5 | AI4 | AI3 | AI2 | AI1 | AI0 | 3.6 | EASY WEB ][ | HTTP://WWW.OLIMEX.COM/DEV | OLIMEX LTD | COPYRIGHT (C) 2004 | +12VDC
bStop: HTTP://WWW.OLIMEX.COM/DEV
